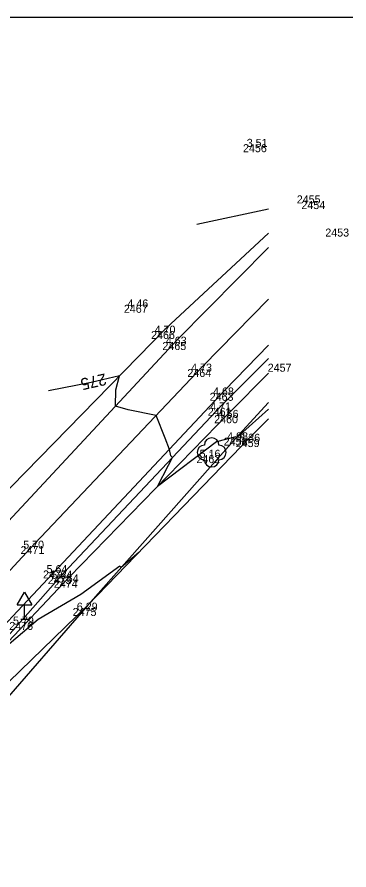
# Model space of a CAD drawing. Extents: x -740053 to -737517, y -1033516 to -1032488.
# Drawn here: x -738633.1 to -738610.3, y -1032595.1 to -1032536.5 of the extents above; entities that cross this region are included whole.
import ezdxf

# ---------------------------------------------------------------- set-up
doc = ezdxf.new("R2010")
doc.units = 0
for name, color, linetype in [('bod-cislo', 7, 'Continuous'), ('bod-oznac', 7, 'Continuous'), ('bod-vyska', 7, 'Continuous'), ('bod-vyska100', 7, 'Continuous'), ('Contours', 7, 'Continuous'), ('Contours highlighted', 7, 'Continuous'), ('Contours text', 7, 'Continuous'), ('dopr-zariz', 7, 'Continuous'), ('osa-komunikace', 7, 'Continuous'), ('ploty', 7, 'Continuous'), ('Predmety bez rozlišeni', 7, 'Continuous'), ('silnice', 7, 'Continuous'), ('Terenni-hrana', 7, 'Continuous'), ('Znacky-kultury', 7, 'Continuous')]:
    doc.layers.add(name, color=color, linetype=linetype)

# ---------------------------------------------------------------- blocks, each defined once
blk = doc.blocks.new('POINT_DISPLAY')
blk.add_line((0, 0), (0, 0))
blk = doc.blocks.new('p_strom')
for centre, start, end in [((0, 1), 0, 180), ((-1, 0), 90, 270), ((1, 0), 270, 90), ((0, -1), 180, 0)]:
    blk.add_arc(centre, 1, start, end)
at = {"rotation": -180}
blk.add_blockref('POINT_DISPLAY', (0, 0), dxfattribs=at)
blk = doc.blocks.new('d_znacka')
for p, q in [((-1, 2), (0, 3.73)), ((0, 3.73), (1, 2)), ((-1, 2), (1, 2)), ((0, 0), (0, 2)), ((-0.5, 0), (0.5, 0))]:
    blk.add_line(p, q)

msp = doc.modelspace()

# ---------------------------------------------------------------- linework, layer by layer
at = {"layer": 'Contours'}
for points in [[(-738615.812, -1032549.676), (-738620.744, -1032550.724)], [(-738624.738, -1032573.29), (-738624.738, -1032573.29), (-738625.932, -1032574.318), (-738626.046, -1032574.213), (-738628.725, -1032576.16), (-738631.65, -1032577.879), (-738634.735, -1032580.5)]]:
    msp.add_lwpolyline(points, dxfattribs=at)
at = {"layer": 'Contours highlighted'}
msp.add_lwpolyline([(-738615.812, -1032563.438), (-738617.807, -1032565.205), (-738618.008, -1032565.379), (-738618.058, -1032565.333), (-738619.395, -1032565.669), (-738623.443, -1032568.738), (-738622.685, -1032567.28), (-738622.425, -1032566.758), (-738622.528, -1032566.636), (-738622.63, -1032566.19), (-738622.914, -1032565.424), (-738623.548, -1032563.868), (-738625.459, -1032563.478), (-738626.331, -1032563.217), (-738626.312, -1032562.108), (-738626.047, -1032561.146), (-738628.002, -1032561.583), (-738630.945, -1032562.158)], dxfattribs=at)
at = {"layer": 'osa-komunikace'}
for p, q in [((-738615.812, -1032555.877), (-738620.33, -1032560.48)), ((-738620.33, -1032560.48), (-738631.89, -1032572.65)), ((-738631.89, -1032572.65), (-738641.93, -1032583.53))]:
    msp.add_line(p, q, dxfattribs=at)
at = {"layer": 'ploty'}
for p, q in [((-738615.812, -1032562.98), (-738617.85, -1032565.2)), ((-738617.85, -1032565.2), (-738628.23, -1032576.91)), ((-738628.23, -1032576.91), (-738644.09, -1032595.1))]:
    msp.add_line(p, q, dxfattribs=at)
at = {"layer": 'Predmety bez rozlišeni'}
msp.add_line((-738715.011, -1032536.475), (-738610.011, -1032536.475), dxfattribs=at)
at = {"layer": 'silnice'}
for p, q in [((-738615.812, -1032552.304), (-738622.06, -1032558.63)), ((-738622.06, -1032558.63), (-738633.72, -1032571.15)), ((-738615.812, -1032559.025), (-738618.81, -1032562.12)), ((-738618.81, -1032562.12), (-738630.27, -1032574.33)), ((-738630.27, -1032574.33), (-738640.35, -1032585.06))]:
    msp.add_line(p, q, dxfattribs=at)
at = {"layer": 'Terenni-hrana'}
for p, q in [((-738615.812, -1032551.333), (-738622.84, -1032557.87)), ((-738622.84, -1032557.87), (-738634.92, -1032570.21)), ((-738615.812, -1032559.942), (-738619.02, -1032563.15)), ((-738615.812, -1032560.952), (-738618.5, -1032563.66)), ((-738619.02, -1032563.15), (-738629.94, -1032574.72)), ((-738618.5, -1032563.66), (-738629.51, -1032574.97)), ((-738615.812, -1032564.081), (-738617.03, -1032565.3)), ((-738617.03, -1032565.3), (-738628.23, -1032576.91)), ((-738629.94, -1032574.72), (-738639.62, -1032585.67)), ((-738629.51, -1032574.97), (-738639.62, -1032585.67)), ((-738628.23, -1032576.91), (-738637.56, -1032585.91))]:
    msp.add_line(p, q, dxfattribs=at)

# ---------------------------------------------------------------- block references
at = {"layer": 'bod-oznac'}
for p in [(-738616.52, -1032545.03), (-738624.71, -1032556.07), (-738622.84, -1032557.87), (-738622.06, -1032558.63), (-738620.33, -1032560.48), (-738618.81, -1032562.12), (-738619.02, -1032563.15), (-738618.5, -1032563.66), (-738617.85, -1032565.2), (-738617.03, -1032565.3), (-738619.72, -1032566.4), (-738631.89, -1032572.65), (-738630.27, -1032574.33), (-738629.94, -1032574.72), (-738629.51, -1032574.97), (-738628.23, -1032576.91), (-738632.59, -1032577.87)]:
    msp.add_blockref('POINT_DISPLAY', p, dxfattribs=at)
at = {"layer": 'dopr-zariz', "xscale": 0.5, "yscale": 0.5}
msp.add_blockref('d_znacka', (-738632.59, -1032577.87), dxfattribs=at)
at = {"layer": 'Znacky-kultury', "xscale": 0.5, "yscale": 0.5}
msp.add_blockref('p_strom', (-738619.72, -1032566.4), dxfattribs=at)

# ---------------------------------------------------------------- texts
at = {"layer": 'bod-cislo'}
for s, p in [('2456', (-738617.568, -1032545.763)), ('2455', (-738613.868, -1032549.283)), ('2454', (-738613.551, -1032549.673)), ('2453', (-738611.908, -1032551.563)), ('2467', (-738625.758, -1032556.803)), ('2466', (-738623.888, -1032558.603)), ('2465', (-738623.108, -1032559.363)), ('2457', (-738615.868, -1032560.853)), ('2464', (-738621.391, -1032561.213)), ('2463', (-738619.858, -1032562.853)), ('2461', (-738619.989, -1032563.883)), ('2460', (-738619.548, -1032564.393)), ('2458', (-738618.898, -1032565.933)), ('2459', (-738618.065, -1032566.033)), ('2462', (-738620.768, -1032567.133)), ('2471', (-738632.859, -1032573.383)), ('2472', (-738631.318, -1032575.063)), ('2473', (-738630.988, -1032575.453)), ('2474', (-738630.571, -1032575.703)), ('2475', (-738629.278, -1032577.643)), ('2476', (-738633.638, -1032578.603))]:
    msp.add_text(s, height=0.55, dxfattribs=at).set_placement(p)
at = {"layer": 'bod-vyska'}
for s, p in [('3 51', (-738617.309, -1032545.397)), ('4 46', (-738625.512, -1032556.437)), ('4 70', (-738623.642, -1032558.237)), ('4 63', (-738622.875, -1032558.997)), ('4 73', (-738621.132, -1032560.847)), ('4 68', (-738619.625, -1032562.487)), ('4 71', (-738619.822, -1032563.517)), ('4 56', (-738619.302, -1032564.027)), ('4 98', (-738618.652, -1032565.567)), ('5 36', (-738617.819, -1032565.667)), ('5 16', (-738620.548, -1032566.767)), ('5 70', (-738632.679, -1032573.017)), ('5 64', (-738631.072, -1032574.697)), ('5 64', (-738630.742, -1032575.087)), ('5 54', (-738630.299, -1032575.337)), ('6 29', (-738628.993, -1032577.277)), ('5 79', (-738633.379, -1032578.237))]:
    msp.add_text(s, height=0.55, dxfattribs=at).set_placement(p)
at = {"layer": 'bod-vyska100'}
for s, p in [('273 51', (-738616.687, -1032545.063)), ('274 46', (-738624.878, -1032556.103)), ('274 70', (-738623.008, -1032557.903)), ('274 63', (-738622.229, -1032558.663)), ('274 73', (-738620.498, -1032560.513)), ('274 68', (-738618.979, -1032562.153)), ('274 71', (-738619.188, -1032563.183)), ('274 56', (-738618.668, -1032563.693)), ('274 98', (-738618.018, -1032565.233)), ('275 36', (-738617.197, -1032565.333)), ('275 16', (-738619.891, -1032566.433)), ('275 70', (-738632.057, -1032572.683)), ('275 64', (-738630.438, -1032574.363)), ('275 64', (-738630.108, -1032574.753)), ('275 54', (-738629.677, -1032575.003)), ('276 29', (-738628.397, -1032576.943)), ('275 79', (-738632.757, -1032577.903))]:
    msp.add_text(s, height=0.05, dxfattribs=at).set_placement(p)
at = {"layer": 'Contours text'}
msp.add_text('275', height=0.8, rotation=192.60805, dxfattribs=at).set_placement((-738627.053, -1032560.961))

doc.saveas('drawing.dxf')
